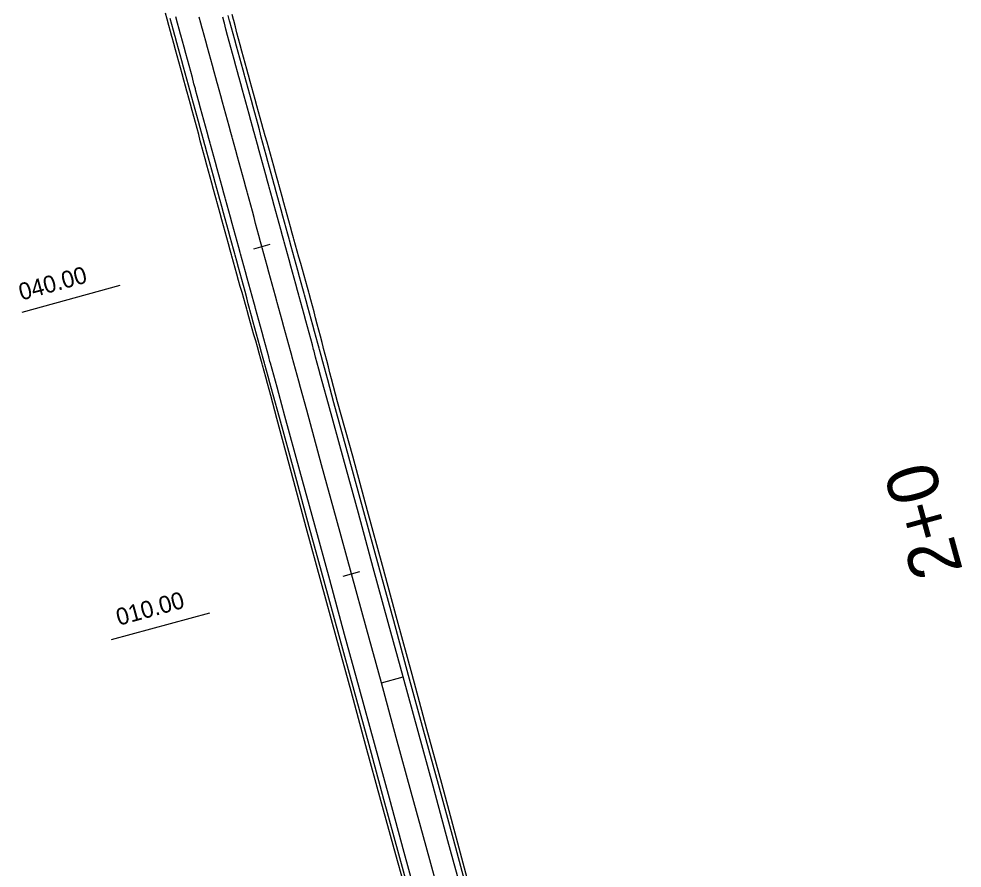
# Model space of a CAD drawing. Extents: x -550605 to -538780, y -1102367 to -1093705.
# Drawn here: x -547597.9 to -547514.5, y -1100296.4 to -1100221.4 of the extents above; entities that cross this region are included whole.
import ezdxf

# ---------------------------------------------------------------- set-up
doc = ezdxf.new("R2010")
doc.units = 0
for name, color, linetype in [('SIT - hrany vozovky', 7, 'Continuous'), ('SIT - osa cesty', 7, 'Continuous'), ('SIT - paty násypů', 7, 'Continuous'), ('SIT - staničení po 100m', 7, 'Continuous'), ('SIT - staničení po 30m', 7, 'Continuous')]:
    doc.layers.add(name, color=color, linetype=linetype)

msp = doc.modelspace()

# ---------------------------------------------------------------- linework, layer by layer
at = {"layer": 'SIT - hrany vozovky'}
for points in [[(-547562.984, -1100300.013), (-547564.304, -1100295.19), (-547565.623, -1100290.367), (-547566.943, -1100285.545), (-547568.263, -1100280.722), (-547569.583, -1100275.899), (-547570.903, -1100271.077), (-547572.223, -1100266.254), (-547573.543, -1100261.431), (-547574.863, -1100256.609), (-547575.413, -1100254.598), (-547575.56, -1100254.062), (-547575.707, -1100253.525), (-547575.854, -1100252.988), (-547576.001, -1100252.452), (-547576.148, -1100251.915), (-547576.183, -1100251.786), (-547576.295, -1100251.379), (-547576.442, -1100250.842), (-547576.588, -1100250.305), (-547576.735, -1100249.769), (-547576.882, -1100249.232), (-547577.029, -1100248.696), (-547577.176, -1100248.159), (-547577.323, -1100247.622), (-547577.47, -1100247.086), (-547577.503, -1100246.964), (-547577.616, -1100246.549), (-547577.763, -1100246.013), (-547577.91, -1100245.476), (-547578.057, -1100244.939), (-547578.204, -1100244.403), (-547578.351, -1100243.866), (-547578.498, -1100243.33), (-547578.645, -1100242.793), (-547578.791, -1100242.256), (-547578.823, -1100242.141), (-547578.938, -1100241.72), (-547579.085, -1100241.183), (-547579.232, -1100240.647), (-547579.379, -1100240.11), (-547579.526, -1100239.573), (-547579.673, -1100239.037), (-547579.82, -1100238.5), (-547579.966, -1100237.964), (-547580.113, -1100237.427), (-547580.143, -1100237.318), (-547580.26, -1100236.89), (-547580.407, -1100236.354), (-547580.554, -1100235.817), (-547580.701, -1100235.281), (-547580.848, -1100234.744), (-547580.994, -1100234.207), (-547581.141, -1100233.671), (-547581.288, -1100233.134), (-547581.435, -1100232.598), (-547581.463, -1100232.496), (-547581.582, -1100232.061), (-547581.729, -1100231.524), (-547581.876, -1100230.988), (-547582.023, -1100230.451), (-547582.169, -1100229.915), (-547582.316, -1100229.378), (-547582.463, -1100228.841), (-547582.61, -1100228.305), (-547582.757, -1100227.768), (-547582.783, -1100227.673), (-547582.904, -1100227.232), (-547583.051, -1100226.695), (-547583.197, -1100226.158), (-547583.344, -1100225.622), (-547583.491, -1100225.085), (-547583.638, -1100224.549), (-547583.785, -1100224.012), (-547583.932, -1100223.475), (-547584.079, -1100222.939), (-547584.103, -1100222.85), (-547584.226, -1100222.402), (-547584.372, -1100221.866), (-547584.519, -1100221.329)], [(-547562.501, -1100299.881), (-547563.821, -1100295.058), (-547565.141, -1100290.235), (-547566.461, -1100285.413), (-547567.781, -1100280.59), (-547569.101, -1100275.767), (-547570.421, -1100270.945), (-547571.741, -1100266.122), (-547573.061, -1100261.299), (-547574.381, -1100256.477), (-547574.931, -1100254.466), (-547575.078, -1100253.93), (-547575.225, -1100253.393), (-547575.372, -1100252.856), (-547575.519, -1100252.32), (-547575.666, -1100251.783), (-547575.701, -1100251.654), (-547575.812, -1100251.247), (-547575.959, -1100250.71), (-547576.106, -1100250.173), (-547576.253, -1100249.637), (-547576.4, -1100249.1), (-547576.547, -1100248.564), (-547576.694, -1100248.027), (-547576.841, -1100247.49), (-547576.987, -1100246.954), (-547577.021, -1100246.832), (-547577.134, -1100246.417), (-547577.281, -1100245.881), (-547577.428, -1100245.344), (-547577.575, -1100244.807), (-547577.722, -1100244.271), (-547577.869, -1100243.734), (-547578.015, -1100243.198), (-547578.162, -1100242.661), (-547578.309, -1100242.124), (-547578.341, -1100242.009), (-547578.456, -1100241.588), (-547578.603, -1100241.051), (-547578.75, -1100240.515), (-547578.897, -1100239.978), (-547579.044, -1100239.441), (-547579.19, -1100238.905), (-547579.337, -1100238.368), (-547579.484, -1100237.832), (-547579.631, -1100237.295), (-547579.661, -1100237.186), (-547579.778, -1100236.758), (-547579.925, -1100236.222), (-547580.072, -1100235.685), (-547580.218, -1100235.149), (-547580.365, -1100234.612), (-547580.512, -1100234.075), (-547580.659, -1100233.539), (-547580.806, -1100233.002), (-547580.953, -1100232.466), (-547580.981, -1100232.364), (-547581.1, -1100231.929), (-547581.247, -1100231.392), (-547581.393, -1100230.856), (-547581.54, -1100230.319), (-547581.687, -1100229.783), (-547581.834, -1100229.246), (-547581.981, -1100228.709), (-547582.128, -1100228.173), (-547582.275, -1100227.636), (-547582.301, -1100227.541), (-547582.421, -1100227.1), (-547582.568, -1100226.563), (-547582.715, -1100226.026), (-547582.862, -1100225.49), (-547583.009, -1100224.953), (-547583.156, -1100224.417), (-547583.303, -1100223.88), (-547583.45, -1100223.343), (-547583.596, -1100222.807), (-547583.621, -1100222.718), (-547583.743, -1100222.27), (-547583.89, -1100221.734), (-547584.037, -1100221.197)], [(-547558.643, -1100298.825), (-547559.963, -1100294.002), (-547561.283, -1100289.179), (-547562.603, -1100284.357), (-547563.923, -1100279.534), (-547565.243, -1100274.711), (-547566.563, -1100269.889), (-547567.883, -1100265.066), (-547569.203, -1100260.244), (-547570.523, -1100255.421), (-547571.073, -1100253.41), (-547571.22, -1100252.874), (-547571.367, -1100252.337), (-547571.514, -1100251.8), (-547571.661, -1100251.264), (-547571.807, -1100250.727), (-547571.843, -1100250.598), (-547571.954, -1100250.191), (-547572.101, -1100249.654), (-547572.248, -1100249.117), (-547572.395, -1100248.581), (-547572.542, -1100248.044), (-547572.689, -1100247.508), (-547572.836, -1100246.971), (-547572.982, -1100246.434), (-547573.129, -1100245.898), (-547573.163, -1100245.776), (-547573.276, -1100245.361), (-547573.423, -1100244.825), (-547573.57, -1100244.288), (-547573.717, -1100243.751), (-547573.864, -1100243.215), (-547574.01, -1100242.678), (-547574.157, -1100242.142), (-547574.304, -1100241.605), (-547574.451, -1100241.068), (-547574.483, -1100240.953), (-547574.598, -1100240.532), (-547574.745, -1100239.995), (-547574.892, -1100239.459), (-547575.039, -1100238.922), (-547575.185, -1100238.385), (-547575.332, -1100237.849), (-547575.479, -1100237.312), (-547575.626, -1100236.776), (-547575.773, -1100236.239), (-547575.803, -1100236.13), (-547575.92, -1100235.702), (-547576.067, -1100235.166), (-547576.213, -1100234.629), (-547576.36, -1100234.093), (-547576.507, -1100233.556), (-547576.654, -1100233.019), (-547576.801, -1100232.483), (-547576.948, -1100231.946), (-547577.095, -1100231.41), (-547577.123, -1100231.308), (-547577.242, -1100230.873), (-547577.388, -1100230.337), (-547577.535, -1100229.8), (-547577.682, -1100229.263), (-547577.829, -1100228.727), (-547577.976, -1100228.19), (-547578.123, -1100227.654), (-547578.27, -1100227.117), (-547578.416, -1100226.58), (-547578.443, -1100226.485), (-547578.563, -1100226.044), (-547578.71, -1100225.507), (-547578.857, -1100224.971), (-547579.004, -1100224.434), (-547579.151, -1100223.897), (-547579.298, -1100223.361), (-547579.445, -1100222.824), (-547579.591, -1100222.288), (-547579.738, -1100221.751), (-547579.762, -1100221.663), (-547579.885, -1100221.214)], [(-547558.161, -1100298.693), (-547559.481, -1100293.87), (-547560.801, -1100289.047), (-547562.121, -1100284.225), (-547563.441, -1100279.402), (-547564.761, -1100274.579), (-547566.081, -1100269.757), (-547567.401, -1100264.934), (-547568.721, -1100260.112), (-547570.041, -1100255.289), (-547570.591, -1100253.278), (-547570.738, -1100252.742), (-547570.885, -1100252.205), (-547571.031, -1100251.668), (-547571.178, -1100251.132), (-547571.325, -1100250.595), (-547571.36, -1100250.466), (-547571.472, -1100250.059), (-547571.619, -1100249.522), (-547571.766, -1100248.985), (-547571.913, -1100248.449), (-547572.06, -1100247.912), (-547572.206, -1100247.376), (-547572.353, -1100246.839), (-547572.5, -1100246.302), (-547572.647, -1100245.766), (-547572.68, -1100245.644), (-547572.794, -1100245.229), (-547572.941, -1100244.693), (-547573.088, -1100244.156), (-547573.234, -1100243.619), (-547573.381, -1100243.083), (-547573.528, -1100242.546), (-547573.675, -1100242.01), (-547573.822, -1100241.473), (-547573.969, -1100240.936), (-547574, -1100240.821), (-547574.116, -1100240.4), (-547574.263, -1100239.863), (-547574.409, -1100239.327), (-547574.556, -1100238.79), (-547574.703, -1100238.253), (-547574.85, -1100237.717), (-547574.997, -1100237.18), (-547575.144, -1100236.644), (-547575.291, -1100236.107), (-547575.32, -1100235.998), (-547575.437, -1100235.57), (-547575.584, -1100235.034), (-547575.731, -1100234.497), (-547575.878, -1100233.961), (-547576.025, -1100233.424), (-547576.172, -1100232.887), (-547576.319, -1100232.351), (-547576.466, -1100231.814), (-547576.612, -1100231.278), (-547576.64, -1100231.176), (-547576.759, -1100230.741), (-547576.906, -1100230.205), (-547577.053, -1100229.668), (-547577.2, -1100229.131), (-547577.347, -1100228.595), (-547577.494, -1100228.058), (-547577.64, -1100227.522), (-547577.787, -1100226.985), (-547577.934, -1100226.448), (-547577.96, -1100226.353), (-547578.081, -1100225.912), (-547578.228, -1100225.375), (-547578.375, -1100224.839), (-547578.522, -1100224.302), (-547578.669, -1100223.765), (-547578.815, -1100223.229), (-547578.962, -1100222.692), (-547579.109, -1100222.156), (-547579.256, -1100221.619), (-547579.28, -1100221.531), (-547579.403, -1100221.082)]]:
    msp.add_lwpolyline(points, dxfattribs=at)
at = {"layer": 'SIT - osa cesty'}
msp.add_lwpolyline([(-547560.572, -1100299.353), (-547561.892, -1100294.53), (-547563.212, -1100289.707), (-547564.532, -1100284.885), (-547565.852, -1100280.062), (-547567.172, -1100275.239), (-547568.492, -1100270.417), (-547569.812, -1100265.594), (-547571.132, -1100260.772), (-547572.452, -1100255.949), (-547573.002, -1100253.938), (-547573.149, -1100253.402), (-547573.296, -1100252.865), (-547573.443, -1100252.328), (-547573.59, -1100251.792), (-547573.737, -1100251.255), (-547573.772, -1100251.126), (-547573.883, -1100250.719), (-547574.03, -1100250.182), (-547574.177, -1100249.645), (-547574.324, -1100249.109), (-547574.471, -1100248.572), (-547574.618, -1100248.036), (-547574.765, -1100247.499), (-547574.911, -1100246.962), (-547575.058, -1100246.426), (-547575.092, -1100246.304), (-547575.205, -1100245.889), (-547575.352, -1100245.353), (-547575.499, -1100244.816), (-547575.646, -1100244.279), (-547575.793, -1100243.743), (-547575.94, -1100243.206), (-547576.086, -1100242.67), (-547576.233, -1100242.133), (-547576.38, -1100241.596), (-547576.412, -1100241.481), (-547576.527, -1100241.06), (-547576.674, -1100240.523), (-547576.821, -1100239.987), (-547576.968, -1100239.45), (-547577.114, -1100238.913), (-547577.261, -1100238.377), (-547577.408, -1100237.84), (-547577.555, -1100237.304), (-547577.702, -1100236.767), (-547577.732, -1100236.658), (-547577.849, -1100236.23), (-547577.996, -1100235.694), (-547578.143, -1100235.157), (-547578.289, -1100234.621), (-547578.436, -1100234.084), (-547578.583, -1100233.547), (-547578.73, -1100233.011), (-547578.877, -1100232.474), (-547579.024, -1100231.938), (-547579.052, -1100231.836), (-547579.171, -1100231.401), (-547579.317, -1100230.864), (-547579.464, -1100230.328), (-547579.611, -1100229.791), (-547579.758, -1100229.255), (-547579.905, -1100228.718), (-547580.052, -1100228.181), (-547580.199, -1100227.645), (-547580.346, -1100227.108), (-547580.372, -1100227.013), (-547580.492, -1100226.572), (-547580.639, -1100226.035), (-547580.786, -1100225.499), (-547580.933, -1100224.962), (-547581.08, -1100224.425), (-547581.227, -1100223.889), (-547581.374, -1100223.352), (-547581.52, -1100222.816), (-547581.667, -1100222.279), (-547581.692, -1100222.191), (-547581.814, -1100221.742), (-547581.961, -1100221.206)], dxfattribs=at)
at = {"layer": 'SIT - paty násypů'}
for points in [[(-547563.225, -1100300.079), (-547564.561, -1100295.26), (-547565.892, -1100290.441), (-547567.212, -1100285.618), (-547568.531, -1100280.795), (-547569.85, -1100275.972), (-547571.169, -1100271.149), (-547572.488, -1100266.327), (-547573.807, -1100261.504), (-547575.102, -1100256.674), (-547575.637, -1100254.659), (-547575.779, -1100254.122), (-547575.922, -1100253.584), (-547576.064, -1100253.046), (-547576.206, -1100252.508), (-547576.359, -1100251.973), (-547576.395, -1100251.844), (-547576.511, -1100251.438), (-547576.663, -1100250.903), (-547576.815, -1100250.368), (-547576.967, -1100249.832), (-547577.119, -1100249.297), (-547577.27, -1100248.762), (-547577.421, -1100248.226), (-547577.572, -1100247.691), (-547577.723, -1100247.155), (-547577.758, -1100247.033), (-547577.874, -1100246.62), (-547578.024, -1100246.084), (-547578.174, -1100245.548), (-547578.324, -1100245.013), (-547578.474, -1100244.477), (-547578.624, -1100243.941), (-547578.773, -1100243.405), (-547578.922, -1100242.869), (-547579.071, -1100242.333), (-547579.103, -1100242.218), (-547579.22, -1100241.797), (-547579.368, -1100241.261), (-547579.517, -1100240.725), (-547579.665, -1100240.188), (-547579.813, -1100239.652), (-547579.961, -1100239.116), (-547580.108, -1100238.579), (-547580.255, -1100238.043), (-547580.402, -1100237.506), (-547580.432, -1100237.398), (-547580.549, -1100236.97), (-547580.696, -1100236.433), (-547580.843, -1100235.896), (-547580.989, -1100235.36), (-547581.135, -1100234.823), (-547581.281, -1100234.286), (-547581.426, -1100233.749), (-547581.572, -1100233.212), (-547581.717, -1100232.675), (-547581.745, -1100232.573), (-547581.862, -1100232.138), (-547582.007, -1100231.601), (-547582.152, -1100231.063), (-547582.296, -1100230.526), (-547582.44, -1100229.989), (-547582.586, -1100229.452), (-547582.735, -1100228.916), (-547582.884, -1100228.38), (-547583.033, -1100227.844), (-547583.059, -1100227.749), (-547583.181, -1100227.308), (-547583.33, -1100226.771), (-547583.478, -1100226.235), (-547583.626, -1100225.699), (-547583.774, -1100225.163), (-547583.921, -1100224.626), (-547584.069, -1100224.09), (-547584.216, -1100223.553), (-547584.363, -1100223.017), (-547584.387, -1100222.928), (-547584.51, -1100222.48), (-547584.656, -1100221.943), (-547584.803, -1100221.407), (-547584.949, -1100220.87)], [(-547557.918, -1100298.626), (-547559.2, -1100293.793), (-547560.491, -1100288.962), (-547561.816, -1100284.141), (-547563.133, -1100279.318), (-547564.442, -1100274.492), (-547565.752, -1100269.667), (-547567.062, -1100264.842), (-547568.372, -1100260.016), (-547569.739, -1100255.206), (-547570.267, -1100253.19), (-547570.397, -1100252.648), (-547570.537, -1100252.11), (-547570.677, -1100251.571), (-547570.817, -1100251.033), (-547570.958, -1100250.495), (-547570.992, -1100250.365), (-547571.099, -1100249.956), (-547571.24, -1100249.418), (-547571.381, -1100248.88), (-547571.522, -1100248.342), (-547571.664, -1100247.804), (-547571.806, -1100247.266), (-547571.947, -1100246.728), (-547572.09, -1100246.19), (-547572.232, -1100245.652), (-547572.264, -1100245.53), (-547572.374, -1100245.114), (-547572.525, -1100244.579), (-547572.677, -1100244.044), (-547572.83, -1100243.509), (-547572.983, -1100242.974), (-547573.136, -1100242.439), (-547573.29, -1100241.904), (-547573.442, -1100241.369), (-547573.589, -1100240.832), (-547573.62, -1100240.717), (-547573.736, -1100240.296), (-547573.883, -1100239.759), (-547574.03, -1100239.223), (-547574.178, -1100238.686), (-547574.326, -1100238.15), (-547574.473, -1100237.614), (-547574.622, -1100237.078), (-547574.77, -1100236.541), (-547574.918, -1100236.005), (-547574.949, -1100235.897), (-547575.067, -1100235.469), (-547575.216, -1100234.933), (-547575.365, -1100234.397), (-547575.515, -1100233.861), (-547575.664, -1100233.325), (-547575.814, -1100232.789), (-547575.964, -1100232.254), (-547576.114, -1100231.718), (-547576.264, -1100231.182), (-547576.293, -1100231.081), (-547576.415, -1100230.647), (-547576.565, -1100230.111), (-547576.716, -1100229.576), (-547576.867, -1100229.04), (-547577.018, -1100228.505), (-547577.167, -1100227.969), (-547577.311, -1100227.431), (-547577.456, -1100226.894), (-547577.601, -1100226.357), (-547577.626, -1100226.262), (-547577.745, -1100225.82), (-547577.891, -1100225.283), (-547578.036, -1100224.746), (-547578.181, -1100224.209), (-547578.327, -1100223.672), (-547578.473, -1100223.135), (-547578.619, -1100222.598), (-547578.765, -1100222.061), (-547578.911, -1100221.525), (-547578.935, -1100221.436), (-547579.058, -1100220.988)]]:
    msp.add_lwpolyline(points, dxfattribs=at)
at = {"layer": 'SIT - staničení po 100m'}
msp.add_lwpolyline([(-547565.852, -1100280.062), (-547563.923, -1100279.534)], dxfattribs=at)
at = {"layer": 'SIT - staničení po 30m'}
for points in [[(-547577.135, -1100241.679), (-547575.688, -1100241.283)], [(-547597.631, -1100247.289), (-547588.951, -1100244.913)], [(-547569.215, -1100270.615), (-547567.769, -1100270.219)], [(-547589.712, -1100276.225), (-547581.031, -1100273.849)]]:
    msp.add_lwpolyline(points, dxfattribs=at)

# ---------------------------------------------------------------- texts
at = {"layer": 'SIT - staničení po 100m'}
msp.add_text('2+0', height=4.5, rotation=105.30701, dxfattribs=at).set_placement((-547514.407, -1100270.098))
at = {"layer": 'SIT - staničení po 30m'}
for s, p in [('040.00', (-547597.685, -1100246.267)), ('010.00', (-547589.071, -1100275.012))]:
    msp.add_text(s, height=1.5, rotation=15.30701, dxfattribs=at).set_placement(p)

doc.saveas('drawing.dxf')
